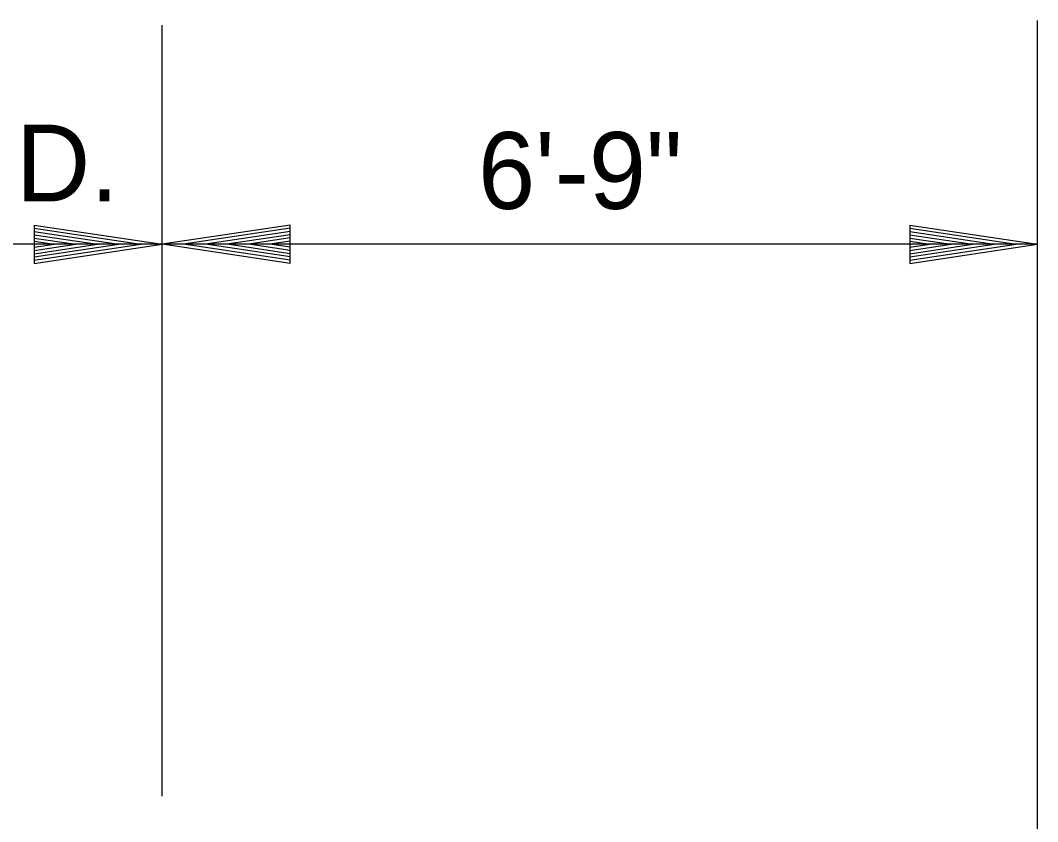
# Model space of a CAD drawing. Extents: x -900 to 15312, y 1857 to 2945.
# Drawn here: x 4203.1 to 4282.6, y 2460.9 to 2523.5 of the extents above; entities that cross this region are included whole.
import ezdxf

# ---------------------------------------------------------------- set-up
doc = ezdxf.new("R2010")
doc.units = 0
doc.layers.add('R_Annotation', color=7, linetype='Continuous')
doc.layers.add('R_Dimension', color=7, linetype='Continuous')

msp = doc.modelspace()

# ---------------------------------------------------------------- linework, layer by layer
at = {"layer": 'R_Dimension'}
for p, q in [((4282.587, 2453.949), (4282.587, 2523.524)), ((4214.164, 2462.895), (4214.164, 2523.146)), ((4204.164, 2507.524), (4214.164, 2506.024)), ((4204.164, 2507.524), (4204.164, 2504.524)), ((4224.164, 2507.524), (4214.164, 2506.024)), ((4224.164, 2504.524), (4224.164, 2507.524)), ((4272.587, 2507.524), (4282.587, 2506.024)), ((4272.587, 2507.524), (4272.587, 2504.524)), ((4204.164, 2507.274), (4212.494, 2506.024)), ((4204.164, 2507.019), (4210.774, 2506.024)), ((4204.164, 2506.769), (4209.109, 2506.024)), ((4224.164, 2507.274), (4215.834, 2506.024)), ((4224.164, 2507.019), (4217.554, 2506.024)), ((4224.164, 2506.769), (4219.219, 2506.024)), ((4272.587, 2507.274), (4280.917, 2506.024)), ((4272.587, 2507.019), (4279.197, 2506.024)), ((4272.587, 2506.769), (4277.532, 2506.024)), ((4282.587, 2506.024), (3845.735, 2506.024)), ((4204.164, 2506.509), (4207.414, 2506.024)), ((4204.164, 2506.259), (4205.744, 2506.024)), ((4204.164, 2504.524), (4214.164, 2506.024)), ((4204.164, 2505.534), (4207.414, 2506.024)), ((4204.164, 2505.029), (4210.774, 2506.024)), ((4204.164, 2504.774), (4212.494, 2506.024)), ((4204.164, 2505.279), (4209.109, 2506.024)), ((4204.164, 2505.789), (4205.744, 2506.024)), ((4224.164, 2504.524), (4214.164, 2506.024)), ((4224.164, 2504.774), (4215.834, 2506.024)), ((4224.164, 2505.029), (4217.554, 2506.024)), ((4224.164, 2505.279), (4219.219, 2506.024)), ((4224.164, 2506.514), (4220.914, 2506.024)), ((4224.164, 2505.539), (4220.914, 2506.024)), ((4224.164, 2506.259), (4222.584, 2506.024)), ((4224.164, 2505.789), (4222.584, 2506.024)), ((4272.587, 2506.509), (4275.837, 2506.024)), ((4272.587, 2506.259), (4274.167, 2506.024)), ((4272.587, 2504.524), (4282.587, 2506.024)), ((4272.587, 2505.534), (4275.837, 2506.024)), ((4272.587, 2505.029), (4279.197, 2506.024)), ((4272.587, 2504.774), (4280.917, 2506.024)), ((4272.587, 2505.279), (4277.532, 2506.024)), ((4272.587, 2505.789), (4274.167, 2506.024))]:
    msp.add_line(p, q, dxfattribs=at)

# ---------------------------------------------------------------- texts
at = {"layer": 'R_Annotation'}
for s, p in [("4' SHLD.", (4178.924, 2509.376)), ('6\'-9"', (4238.857, 2508.79))]:
    msp.add_text(s, height=6, dxfattribs=at).set_placement(p)

doc.saveas('drawing.dxf')
